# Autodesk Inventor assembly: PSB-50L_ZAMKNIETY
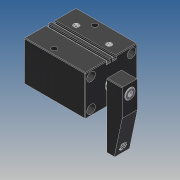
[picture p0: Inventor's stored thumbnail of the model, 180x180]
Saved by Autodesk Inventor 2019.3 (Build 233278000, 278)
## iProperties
Created: 2010-02
Part Number: PSB-50L_ZAMKNIETY
Material: Ogólny
Document SubType Name: Assembly
Designer: CADENGINEERING4
Sending System: PRO/ENGINEER BY PARAMETRIC TECHNOLOGY CORPORATION, 2007170
Preprocessor: PRO/ENGINEER BY PARAMETRIC TECHNOLOGY CORPORATION, 2007170
Title: PSB-50_ASM
Author: Administrator
Revision Number: 1LAST_VERSION
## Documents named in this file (6)
- E:\SERWER_ZAPAS\Pneumatic\PSB PNEUMATIC SWING\PSB-50\PSB-50L_ZAMKNIETY.iam
- E:\SERWER_ZAPAS\Pneumatic\PSB PNEUMATIC SWING\PSB-50\PSB-50BT.ipt
- E:\SERWER_ZAPAS\Pneumatic\PSB PNEUMATIC SWING\PSB-50\PSB-50HSG.ipt
- E:\SERWER_ZAPAS\Pneumatic\PSB PNEUMATIC SWING\PSB-50\PSB-50HG.ipt
- E:\SERWER_ZAPAS\Pneumatic\PSB PNEUMATIC SWING\PSB-50\PSB-50YB.ipt
- E:\SERWER_ZAPAS\Pneumatic\PSB PNEUMATIC SWING\PSB-50\M10LC.ipt
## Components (5 placed, 5 different names)
1. PSB-50BT_0 — Zestawiające:6, Kątowe:1
2. PSB-50HSG_1 — Zestawiające:1, Zestawiające:4, Zestawiające:6, Zestawiające:7
3. PSB-50HG_2 — Zestawiające:7
4. PSB-50YB_3 — Zestawiające:1, Zestawiające:2, Zestawiające:4, Zestawiające:5, Kątowe:1
5. M10LC_4 — Zestawiające:2, Zestawiające:5
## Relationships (7: Mate 6, Angle 1)
- Zestawiające:1 [Mate]: PSB-50HSG_1 ↔ PSB-50YB_3
- Zestawiające:2 [Mate]: PSB-50YB_3 ↔ M10LC_4
- Zestawiające:4 [Mate]: PSB-50HSG_1 ↔ PSB-50YB_3
- Zestawiające:5 [Mate]: PSB-50YB_3 ↔ M10LC_4
- Zestawiające:6 [Mate]: PSB-50BT_0 ↔ PSB-50HSG_1
- Zestawiające:7 [Mate]: PSB-50HSG_1 ↔ PSB-50HG_2
- Kątowe:1 [Angle]: PSB-50BT_0 ↔ PSB-50YB_3
